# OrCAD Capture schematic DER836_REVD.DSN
size Custom; title: USBPD DER-836; rev: D
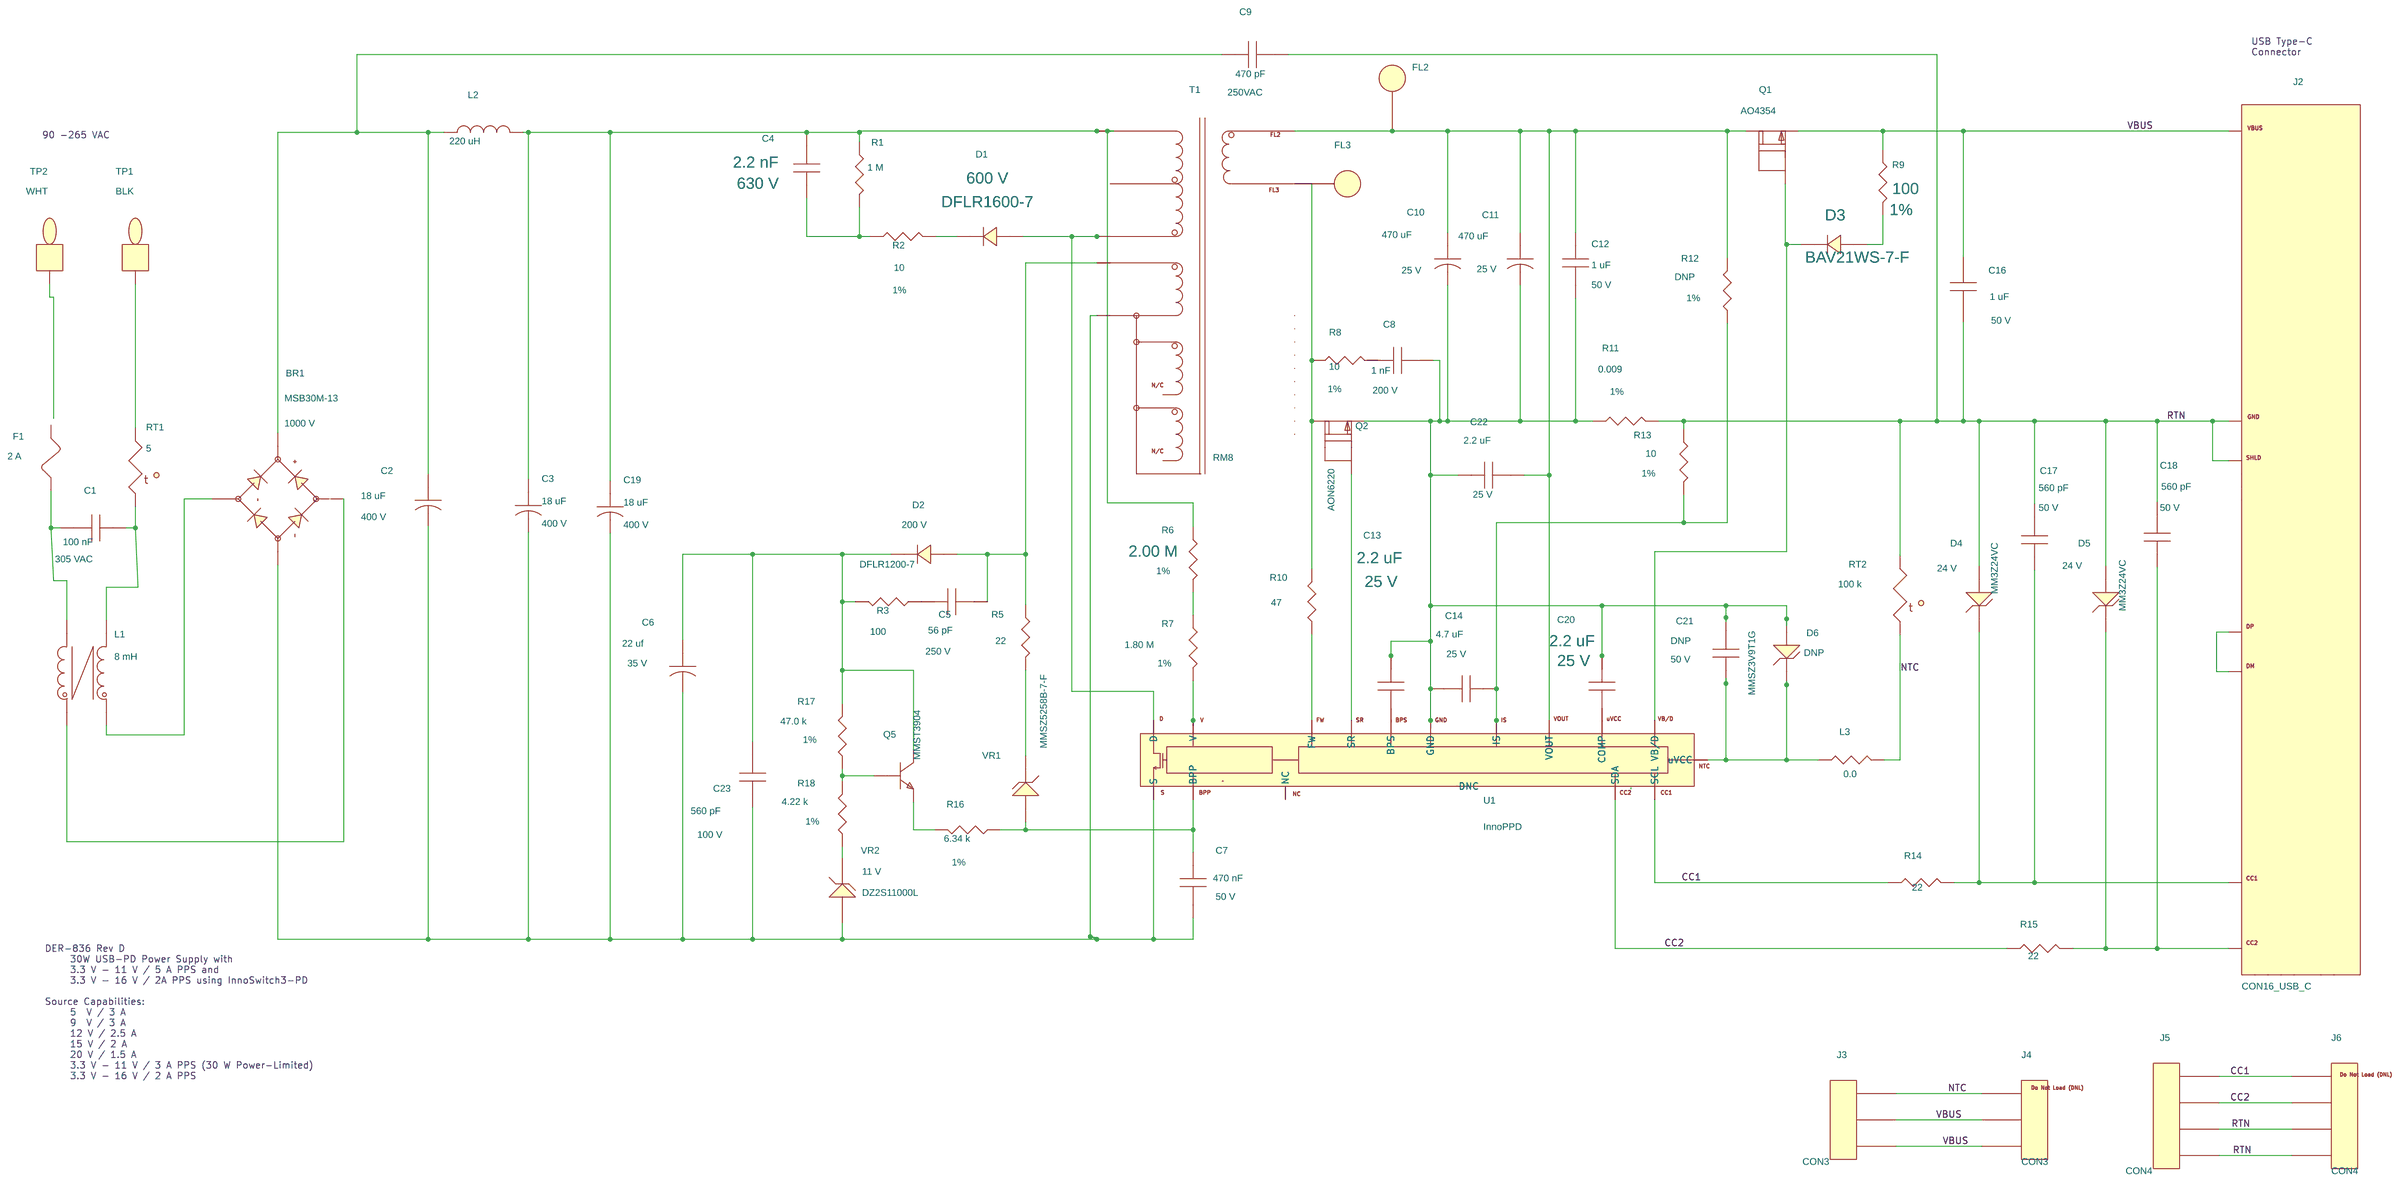
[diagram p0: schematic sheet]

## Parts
BR1  MSB30M-13  [pismd_4SMD_DF-S]
C1  100 nF  [pi_np_xcap_rad512x197x395d040]
C2  18 uF  [pipolcapcyld3p5ls17ld40]
C3  18 uF  [pipolcapcyld3p5ls17ld40]
C4  2.2 nF  [pismc1206]
C5  56 pF  [pismc0603]
C6  22 uf  [pipolcap4p0x11p0xls1p5d030]
C7  470 nF  [pismc0805]
C8  1 nF  [pismc0805]
C9  470 pF  [pinpcapraD7mmxLS10mm030]
C10  470 uF  [pipolcapcyld250ls100030]
C11  470 uF  [pipolcapcyld250ls100030]
C12  1 uF  [pismc0805]
C13  2.2 uF  [pismc0805]
C14  4.7 uF  [pismc0805]
C16  1 uF  [pismc0805]
C17  560 pF  [pismc0603]
C18  560 pF  [pismc0603]
C19  18 uF  [pipolcapcyld3p5ls17ld40]
C20  2.2 uF  [pismc0805]
C21  DNP  [pismc0603]
C22  2.2 uF  [pismc0805]
C23  560 pF  [pismc0805]
D1  DFLR1600-7  [pismddflr120012]
D2  DFLR1200-7  [pismddflr120012]
D3  BAV21WS-7-F  [pismsod323]
D4  MM3Z24VC  [pismsod323F]
D5  MM3Z24VC  [pismsod323F]
D6  MMSZ3V9T1G  [pi_sm_sod-123_12]
F1  2 A  [pi_rst_microfuse]
FL2  Hole_70mils  [pi_hole_70mil]
FL3  Hole_70mils  [pi_hole_70mil]
J2  CON16_USB_C  [USB_C_LM_U3231-096]
J3  CON3  [pi_hdr_1p27mm_3RA]
J4  CON3  [pi_hdr_1p27mm_3RA_DNL]
J5  CON4  [pi_hdr_1p27mm_4RA]
J6  CON4  [pi_hdr_1p27mm_4RA_DNL]
L1  8 mH  [pi_toroid_CMC12x6_4p_V]
L2  220 uH  [pi_choke_2p_ls118d283]
L3  0.0  [pismr0805]
Q1  AO4354  [pismso8]
Q2  AON6220  [pismpqfn5x6b]
Q5  MMST3904  [pismsot323132]
R1  1 M  [pismr1206]
R2  10  [pismr1206]
R3  100  [pismr0402]
R5  22  [pismr0402]
R6  2.00 M  [pismr1206]
R7  1.80 M  [pismr1206]
R8  10  [pismr0805]
R9  100  [pismr0603]
R10  47  [pismr0402]
R11  0.009  [pismr0805]
R12  DNP  [pismr0402]
R13  10  [pismr0402]
R14  22  [pismr0402]
R15  22  [pismr0402]
R16  6.34 k  [pismr0402]
R17  47.0 k  [pismr0402]
R18  4.22 k  [pismr0402]
RT1  5  [pi_rad_276DX197T_ls100d025]
RT2  100 k  [pismr0603]
T1  RM8  [pi_bobbin_rm8_12p_14]
TP1  BLK  [pitpkeystone100x100]
TP2  WHT  [pitpkeystone100x100]
U1  InnoPPD  [pi_ic_insop_24D]
VR1  MMSZ5258B-7-F  [pi_sm_sod-123_12]
VR2  DZ2S11000L  [pi_sm_d_ssmini2p]

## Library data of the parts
BR1 = DIODE_BRIDGE_+~-~: Disp_Voltage: 1000 V; Part Number: 15-01320-00
C1 = CAP_NP: ALT_SYMBOLS: pi_np_xcap_rad512x197x395d040_h; Disp_Voltage: 305 VAC; FPLIST: pi_np_xcap_rad512x197x395d040,pi_np_xcap_rad512x197x395d040_h; Part Number: 20-08957-00; ROOM: 1; Voltage: 305 VAC
C2 C3 C19 = CAP_POL: ALT_SYMBOLS: pipolcapcyld3p5ls17ld40H; Disp_Voltage: 400 V; FPLIST: pipolcapcyld3p5ls17ld40,pipolcapcyld3p5ls17ld40H; Part Number: 20-01380-00; ROOM: 1; Voltage: 400 V
C4 = CAP_NP: Disp_Voltage: 630 V; Part Number: 20-08609-00; ROOM: 1; Voltage: 630 V
C5 = CAP_NP: Disp_Voltage: 250 V; Part Number: 20-01325-00; ROOM: 1; Voltage: 250 V
C6 = CAP_POL: ALT_SYMBOLS: pipolcap4p0x12p5xls1p5d030h; Disp_Voltage: 35 V; FPLIST: pipolcap4p0x11p0xls1p5d030,pipolcap4p0x12p5xls1p5d030h; Part Number: 20-01139-00; ROOM: 1; Voltage: 35 V
C7 = CAP_NP: Disp_Voltage: 50 V; Part Number: 20-00896-00; ROOM: 1; Voltage: 50 V
C8 = CAP_NP: ALT_SYMBOLS: pismc0805_1; Disp_Voltage: 200 V; PCB Editor PCBFP: pismc0603; Part Number: 20-00737-00; Voltage: 200 V
C9 = CAP_NP: Disp_Voltage: 250VAC; Part Number: 20-01454-00; Voltage: 250VAC
C10 C11 = CAP_POL: ALT_SYMBOLS: pipolcapcyld250ls100030_h; Disp_Voltage: 25 V; FPLIST: pipolcapcyld250ls100030,pipolcapcyld250ls100030_h; Part Number: 20-01383-00; Voltage: 25 V
C12 C16 = CAP_NP: Disp_Voltage: 50 V; Part Number: 20-09146-00; Voltage: 50 V
C13 C20 C22 = CAP_NP: Disp_Voltage: 25 V; Part Number: 20-08603-00; Voltage: 25 V
C14 = CAP_NP: Disp_Voltage: 25 V; Part Number: 20-09022-00; Voltage: 25 V
C17 C18 C21 = CAP_NP: Disp_Voltage: 50 V; Part Number: 20-01450-00; Voltage: 50 V
C23 = CAP_NP: Disp_Voltage: 100 V; PCB Editor PCBFP: pismc0603; Part Number: 20-09240-00; Voltage: 100 V
D1 = DIODE: Disp_Voltage: 600 V; Part Number: 15-00826-00; ROOM: 1
D2 = DIODE: COMPGROUP: 1; Disp_Voltage: 200 V; Part Number: 15-01019-00; ROOM: 1
D3 = DIODE: COMPGROUP: 1; Part Number: 15-00385-00
D4 D5 = DIODE_ZENER: Disp_Voltage: 24 V; Part Number: 15-01590-00
D6 = DIODE_ZENER: Disp_Voltage: DNP; Part Number: 15-01233-00
F1 = FUSE: ALT_SYMBOLS: pirstmicrofusehoz; FPLIST: pi_rst_microfuse,pirstmicrofusehoz; Part Number: 40-00021-00; ROOM: 1
FL2 FL3 = FlyingLead: Part Number: 35-00282-00
J2 = USB_C_LM_U3231-096NSD_20: Part Number: 35-00503-00
J3 = CON3: ALT_SYMBOLS: pi_hdr_1p27mm_3RA_MB,pi_hdr_1p27mm_3RA_DNL; FPLIST: pi_hdr_1p27mm_3RA,pi_hdr_1p27mm_3RA_MB,pi_hdr_1p27mm_3RA_DNL; Part Number: 35-00481-00
J4 = CON3DNL: ALT_SYMBOLS: pi_hdr_1p27mm_3RA_MB,pi_hdr_1p27mm_3RA_DNL; FPLIST: pi_hdr_1p27mm_3RA,pi_hdr_1p27mm_3RA_MB,pi_hdr_1p27mm_3RA_DNL; Part Number: 35-00481-00
J5 = CON4: ALT_SYMBOLS: pi_hdr_1p27mm_4RA_MB,pi_hdr_1p27mm_4RA_DNL; FPLIST: pi_hdr_1p27mm_4RA,pi_hdr_1p27mm_4RA_MB,pi_hdr_1p27mm_4RA_DNL; Part Number: 35-00500-00
J6 = CON4DNL: ALT_SYMBOLS: pi_hdr_1p27mm_4RA_MB,pi_hdr_1p27mm_4RA_DNL; FPLIST: pi_hdr_1p27mm_4RA,pi_hdr_1p27mm_4RA_MB,pi_hdr_1p27mm_4RA_DNL; Part Number: 35-00500-00
L1 = TORRID_4P_21_34: ALT_SYMBOLS: pi_toroid_CMC12x6_4p_H; FPLIST: pi_toroid_CMC12x6_4p_V,pi_toroid_CMC12x6_4p_H; Part Number: 30-04109-00
L2 = INDUCTOR: ALT_SYMBOLS: pi_choke_2p_ls118d283H; FPLIST: pi_choke_2p_ls118d283,pi_choke_2p_ls118d283H; Part Number: 30-00382-00; ROOM: 1
L3 = R: ALT_SYMBOLS: pismr0805_1; COMPGROUP: 1; FPLIST: pismr0805,pismr0805_1; Part Number: 05-03159-00
Q1 = FET_N_SGD_123_4_5678: Part Number: 50-00260-00
Q2 = FET_N_SGD_123_4_5678: Part Number: 50-00276-00; ROOM: 2
Q5 = NPN_BEC: Part Number: 55-00016-00; ROOM: 1
R1 = R: Part Number: 05-01424-00; ROOM: 1
R2 = R: Disp_Tol: 1%; Part Number: 05-00001-00; ROOM: 1
R3 = R: Part Number: 05-06192-00; ROOM: 1
R5 = R: Part Number: 05-06177-00; ROOM: 1
R6 = R: COMPGROUP: 1; Disp_Tol: 1%; Part Number: 05-03156-00; ROOM: 1
R7 = R: COMPGROUP: 1; Disp_Tol: 1%; Part Number: 05-03155-00; ROOM: 1
R8 = R: Disp_Tol: 1%; Part Number: 05-00492-00
R9 = R: Disp_Tol: 1%; Part Number: 05-00982-00
R10 = R: Part Number: 05-03426-00
R11 = R: Disp_Tol: 1%; Part Number: 05-06508-00
R12 = R: Disp_Tol: 1%; Part Number: 05-06057-00
R13 = R: Disp_Tol: 1%; Part Number: 05-05596-00
R14 R15 = R: COMPGROUP: 1; Part Number: 05-06177-00
R16 = R: Disp_Tol: 1%; Part Number: 05-05914-00; ROOM: 1
R17 = R: Disp_Tol: 1%; Part Number: 05-06004-00; ROOM: 1
R18 = R: Disp_Tol: 1%; Part Number: 05-05893-00; ROOM: 1
RT1 = THERMISTOR: ALT_SYMBOLS: pi_rad_276DX197Tls100d025H; FPLIST: pi_rad_276DX197T_ls100d025,pi_rad_276DX197Tls100d025H; Part Number: 91-00009-00; ROOM: 1
RT2 = THERMISTOR: Part Number: 90-00078-00
T1 = Transformer_Main_DER836_REVD: Part Number: 25-01185-00
TP1 = TESTPOINT: Part Number: 35-00079-00; ROOM: 1
TP2 = TESTPOINT: Part Number: 35-00081-00; ROOM: 1
U1 = DEV_InnoPPD: Part Number: 10-01138-00; ROOM: 1
VR1 = DIODE_ZENER: Part Number: 15-01098-00; ROOM: 1
VR2 = DIODE_ZENER: Disp_Voltage: 11 V; Part Number: 15-00931-00; ROOM: 1

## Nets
VBUS: C16.1 J2.A9B4(11) J3.2 J3.3 J4.2 J4.3 Q1.1(S) R9.2
CC1: J5.1 J6.1 R14.2 U1.4(SCL)
CC2: J5.2 J6.2 R15.2 U1.3(SDA)
NTC: J3.1 J4.1 L3.1 RT2.2
RTN: C9.2 C16.2 C17.2 C18.2 D4.2 D5.2 J2.A1B12(1) J2.S1 J5.3 J5.4 J6.3 J6.4 R11.2 R13.2 RT2.1
N2052921: C10.1 C11.1 C12.1 C22.2 FL2.1 Q1.5(D) R12.1 U1.10(VOUT)
N2239928: D1.2 T1.11 U1.24(D)
N2245604: FL3.1 Q2.5(D) R8.2 R10.1
N2248893: C8.2 C10.2 C11.2 C12.2 C13.1 C14.2 C20.1 C21.2 C22.1 D6.2 Q2.1(S) R11.1 U1.2(GND)
N2254675: C4.1 R1.1 R2.2
N2666518: R10.2 U1.11(FW)
N2729572: Q2.4(G) U1.9(SR)
N2741729: D1.1 R2.1
N2930599: BR1.1 C2.1 C9.1 L2.2
N2930737: BR1.2 L1.3
N2993096: C6.1 C23.2 D2.1 Q5.3(COLLECTOR) R3.1 R17.1
N2993205: R5.2 VR1.1
N11157505: C13.2 U1.5(BPS)
N11379484: C3.1 C4.2 C19.1 L2.1 R1.2 R6.2 T1.12
N11391845: C7.1 R16.1 U1.14(BPP) VR1.2
N11927756: D3.2 R9.1
N12067975: D3.1 Q1.4(G) U1.8(VB/D)
N12141120: C14.1 R12.2 R13.1 U1.1(IS)
N12179865: BR1.4 L1.2
N12190252: RT1.1 TP1.1
N12194815: C1.2 F1.1 L1.4
N12195805: C1.1 L1.1 RT1.2
N12223753: C21.1 D6.1 L3.2 U1.6(uVCC)
N12224616: C20.2 U1.7(COMP)
N12350626: C5.2 D2.2 R5.1 T1.1
N12362261: Q5.1(BASE) R17.2 R18.1
N12362291: Q5.2(EMITTER) R16.2
N12362317: R18.2 VR2.1
N12386710: BR1.3 C2.2 C3.2 C6.2 C7.2 C19.2 C23.1 T1.2 U1.16(S) VR2.2
N12437849: C17.1 D4.1 J2.A5(4) R14.1
N12438682: C18.1 D5.1 J2.B5(10) R15.1
N12441472: J2.A6(6) J2.A7(7)
N12461050: R6.1 R7.2
N12463146: C5.1 R3.2
N12463951: R7.1 U1.13(V)
N12465182: C8.1 R8.1

Not connected (* = marked no-connect by the designer): F1 2; J2 A4B9(2) A8(9) A12B1(12) B6(8) B7(5) B8(3) S2 S3 S4; Q1 2(S2) 3(S3) 6(D6) 7(D7) 8(D8); Q2 2(S2) 3(S3) 6(D6) 7(D7) 8(D8); T1 3 4 5 6 7 8 9 10 13 14; TP2 1; U1 12(DNC) 15(NC)

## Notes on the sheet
- USB Type-C
  Connector
- 90 -265 VAC
- DER-836 Rev D
       30W USB-PD Power Supply with
       3.3 V - 11 V / 5 A PPS and
       3.3 V - 16 V / 2A PPS using InnoSwitch3-PD
  Source Capabilities:
       5  V / 3 A
       9  V / 3 A
       12 V / 2.5 A
       15 V / 2 A
       20 V / 1.5 A
       3.3 V - 11 V / 3 A PPS (30 W Power-Limited)
       3.3 V - 16 V / 2 A PPS
